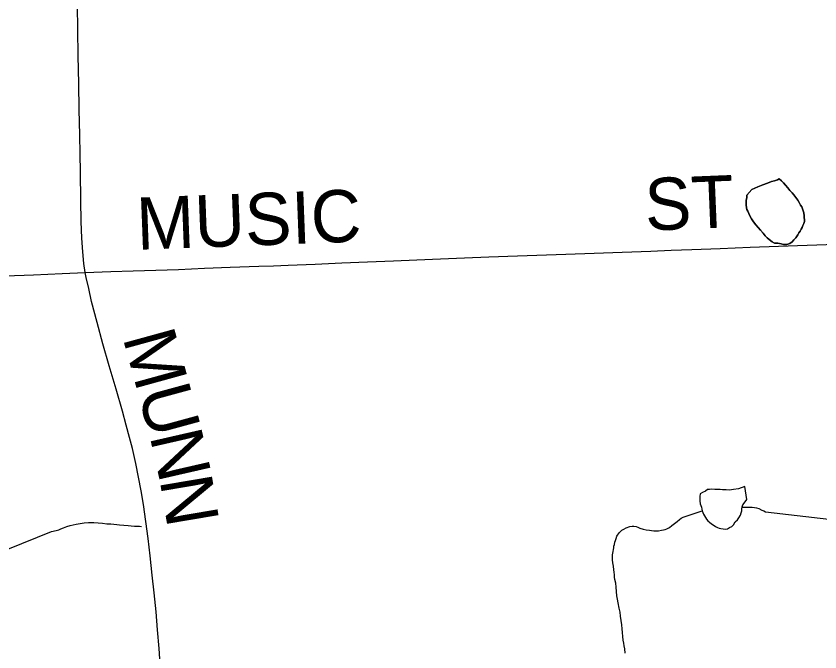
# Model space of a CAD drawing. Extents: x 103424 to 290657, y 38711 to 110967.
# Drawn here: x 126106 to 130753, y 49490 to 53166 of the extents above; entities that cross this region are included whole.
import ezdxf

# ---------------------------------------------------------------- set-up
doc = ezdxf.new("R2010")
doc.units = 0
for name, color, linetype in [('GM_X_Minor_Lake', 7, 'Continuous'), ('GM_X_Minor_River', 7, 'Continuous'), ('GM_X_Township_Road', 7, 'Continuous'), ('GM_X_Township_Road_Text', 7, 'Continuous')]:
    doc.layers.add(name, color=color, linetype=linetype)

msp = doc.modelspace()

# ---------------------------------------------------------------- linework, layer by layer
at = {"layer": 'GM_X_Minor_Lake'}
for points in [[(130359.8, 52163), (130393.8, 52179.7), (130423.9, 52190.3), (130450, 52200.8), (130474.1, 52209.3), (130490.1, 52213.6), (130508.2, 52219.9), (130518.2, 52224.2), (130530.5, 52214.2), (130542.8, 52202.3), (130555.1, 52188.4), (130567.5, 52172.4), (130579.9, 52158.5), (130592.2, 52144.6), (130602.5, 52132.6), (130614.9, 52116.6), (130625.2, 52102.7), (130633.5, 52088.7), (130641.8, 52072.6), (130648.1, 52062.6), (130652.3, 52052.6), (130660.7, 52028.5), (130663.1, 52010.4), (130663.2, 52000.3), (130663.4, 51990.2), (130663.6, 51978.1), (130659.8, 51965.9), (130653.9, 51955.7), (130650.1, 51943.5), (130644.2, 51933.3), (130638.3, 51923.1), (130632.4, 51912.9), (130626.6, 51900.7), (130614.7, 51884.3), (130602.8, 51872), (130592.9, 51861.8), (130579, 51851.4), (130562.9, 51845.1), (130542.8, 51844.8), (130528.6, 51848.6), (130510.3, 51852.3), (130490.1, 51854), (130477.9, 51859.9), (130459.5, 51873.7), (130449.3, 51883.6), (130437, 51895.6), (130424.6, 51911.5), (130410.2, 51927.4), (130395.8, 51943.4), (130383.4, 51959.3), (130369, 51977.3), (130358.6, 51993.3), (130348.2, 52011.3), (130342, 52025.3), (130335.7, 52037.3), (130331.5, 52047.4), (130329.3, 52057.4), (130327, 52075.6), (130326.5, 52101.8), (130330.3, 52116), (130330.1, 52130.2), (130359.8, 52163)], [(130638.3, 51923.1), (130644.2, 51933.3), (130650.1, 51943.5), (130653.9, 51955.7), (130659.8, 51965.9), (130663.6, 51978.1), (130663.4, 51990.2), (130663.2, 52000.3), (130663.1, 52010.4), (130660.7, 52028.5), (130652.3, 52052.6), (130648.1, 52062.6), (130641.8, 52072.6), (130633.5, 52088.7), (130625.2, 52102.7), (130614.9, 52116.6), (130602.5, 52132.6), (130592.2, 52144.6), (130579.9, 52158.5), (130567.5, 52172.4), (130555.1, 52188.4), (130542.8, 52202.3), (130530.5, 52214.2), (130518.2, 52224.2), (130508.2, 52219.9), (130490.1, 52213.6), (130474.1, 52209.3), (130450, 52200.8), (130423.9, 52190.3), (130393.8, 52179.7), (130359.8, 52163)], [(130359.8, 52163), (130330.1, 52130.2), (130330.3, 52116), (130326.5, 52101.8), (130327, 52075.6), (130329.3, 52057.4), (130331.5, 52047.4), (130335.7, 52037.3), (130342, 52025.3), (130348.2, 52011.3), (130358.6, 51993.3), (130369, 51977.3), (130383.4, 51959.3), (130395.8, 51943.4), (130410.2, 51927.4), (130424.6, 51911.5), (130437, 51895.6), (130449.3, 51883.6), (130459.5, 51873.7), (130477.9, 51859.9), (130490.1, 51854), (130510.3, 51852.3), (130528.6, 51848.6), (130542.8, 51844.8), (130562.9, 51845.1), (130579, 51851.4), (130592.9, 51861.8), (130602.8, 51872), (130614.7, 51884.3), (130626.6, 51900.7), (130632.4, 51912.9), (130638.3, 51923.1)], [(130320.1, 50445.3), (130282, 50432.5), (130253.8, 50428), (130229.7, 50425.6), (130211.5, 50427.3), (130189.3, 50427), (130177.1, 50428.8), (130163, 50428.6), (130144.9, 50428.3), (130126.7, 50430), (130114.6, 50429.8), (130102.5, 50429.6), (130092.5, 50419.3), (130074.5, 50411), (130060.5, 50404.7), (130058.8, 50388.5), (130059.2, 50364.2), (130061.5, 50346.1), (130065.7, 50336.1), (130067.9, 50326), (130070.1, 50315.9), (130072.3, 50305.9), (130076.5, 50295.8), (130080.7, 50285.8), (130086.9, 50275.8), (130097.3, 50257.8)], [(130320.1, 50445.3), (130282, 50432.5), (130253.8, 50428), (130229.7, 50425.6), (130211.5, 50427.3), (130189.3, 50427), (130177.1, 50428.8), (130163, 50428.6), (130144.9, 50428.3), (130126.7, 50430), (130114.6, 50429.8), (130102.5, 50429.6), (130092.5, 50419.3), (130074.5, 50411), (130060.5, 50404.7), (130058.8, 50388.5), (130059.2, 50364.2), (130061.5, 50346.1), (130065.7, 50336.1), (130067.9, 50326), (130070.1, 50315.9), (130072.3, 50305.9), (130076.5, 50295.8), (130080.7, 50285.8), (130086.9, 50275.8), (130097.3, 50257.8), (130105.5, 50247.8), (130115.8, 50239.9), (130126, 50230), (130136.2, 50224.1), (130150.5, 50214.2), (130160.7, 50208.3), (130170.8, 50204.5), (130180.9, 50202.6), (130193.1, 50200.8), (130209.3, 50199), (130219.3, 50201.2), (130231.3, 50209.5), (130243.3, 50215.8), (130253.2, 50224), (130263, 50242.3), (130277, 50252.7), (130284.8, 50264.9), (130294.6, 50281.2), (130298.5, 50293.4), (130302.3, 50305.6), (130302.1, 50317.7), (130304, 50327.8), (130307.8, 50340), (130321.6, 50358.4), (130331.5, 50370.7), (130320.1, 50445.3)], [(130097.3, 50257.8), (130105.5, 50247.8), (130115.8, 50239.9), (130126, 50230), (130136.2, 50224.1), (130150.5, 50214.2), (130160.7, 50208.3), (130170.8, 50204.5), (130180.9, 50202.6), (130193.1, 50200.8), (130209.3, 50199), (130219.3, 50201.2), (130231.3, 50209.5), (130243.3, 50215.8), (130253.2, 50224), (130263, 50242.3), (130277, 50252.7), (130284.8, 50264.9), (130294.6, 50281.2), (130298.5, 50293.4), (130302.3, 50305.6), (130302.1, 50317.7), (130304, 50327.8), (130307.8, 50340), (130321.6, 50358.4), (130331.5, 50370.7), (130320.1, 50445.3)]]:
    msp.add_lwpolyline(points, dxfattribs=at)
at = {"layer": 'GM_X_Minor_River'}
for points in [[(129628.1, 49482.5), (129625.6, 49506.7), (129621.3, 49524.8), (129619, 49540.9), (129616.7, 49557.1), (129614.3, 49579.3), (129611.9, 49601.4), (129609.5, 49623.6), (129607.2, 49645.8), (129604.7, 49672), (129600.3, 49696.2), (129597.8, 49720.4), (129593.4, 49742.5), (129586.9, 49772.7), (129582.4, 49794.9), (129580.1, 49815), (129577.7, 49839.2), (129575.2, 49863.4), (129572.8, 49887.6), (129568.4, 49907.8), (129566.2, 49921.9), (129565.9, 49936), (129563.7, 49950.1), (129561.4, 49964.2), (129559, 49986.4), (129556.7, 50004.5), (129554.4, 50022.7), (129554.1, 50038.8), (129553.9, 50050.9), (129555.8, 50061.1), (129557.6, 50071.2), (129559.4, 50081.3), (129561.3, 50091.5), (129561.1, 50101.6), (129565, 50111.7), (129566.8, 50123.9), (129570.7, 50134), (129574.5, 50146.2), (129578.3, 50158.4), (129592.1, 50178.8), (129608, 50193.2), (129620, 50199.5), (129634, 50207.8), (129654.1, 50214.2), (129668.2, 50216.4), (129678.3, 50216.6), (129690.4, 50214.8), (129700.5, 50210.9), (129712.7, 50205), (129731, 50199.3), (129749.2, 50195.5), (129767.4, 50193.8), (129779.6, 50192), (129793.7, 50190.2), (129819.9, 50190.6), (129838.1, 50193), (129848.1, 50195.1), (129858.2, 50197.3), (129868.2, 50201.5), (129884.2, 50209.9), (129898.1, 50220.2), (129912.1, 50232.5), (129928, 50242.9), (129941.9, 50255.3), (129951.9, 50263.5), (129961.9, 50269.7), (130072.3, 50305.9)], [(130303.9, 50327.5), (130348.4, 50326.6), (130362.5, 50326.8), (130374.6, 50325), (130386.8, 50323.1), (130401, 50319.3), (130417.3, 50309.5), (130429.4, 50305.7), (130439.6, 50299.8)], [(130439.6, 50299.8), (130805.6, 50257.3)], [(126058.3, 50084.6), (126310.8, 50185.6), (126336.9, 50192.1), (126353, 50196.4), (126365, 50200.7), (126379.1, 50207), (126399.1, 50215.4), (126419.2, 50219.8), (126435.3, 50224.1), (126453.4, 50228.4), (126475.5, 50232.8), (126499.7, 50235.2), (126523.8, 50237.6), (126556.1, 50238.1), (126580.4, 50236.5), (126604.6, 50234.9), (126630.9, 50231.3), (126653.1, 50229.6), (126671.3, 50227.9), (126687.5, 50226.2), (126703.7, 50224.4), (126754.2, 50221.2), (126770.3, 50219.4), (126790.5, 50217.8), (126806.7, 50216), (126818.8, 50216.2), (126831, 50214.4)]]:
    msp.add_lwpolyline(points, dxfattribs=at)
at = {"layer": 'GM_X_Township_Road'}
for points in [[(126940.8, 49388.5), (126932.5, 49508.7), (126923.7, 49618.1), (126914.9, 49722.3), (126904, 49831.7), (126892.6, 49934.3), (126880.7, 50045.2), (126869.3, 50146.3), (126856.8, 50244.8), (126842.8, 50341.2), (126828.8, 50421), (126814.4, 50499.3), (126798.3, 50579.6), (126778.6, 50666.7), (126762, 50729.9), (126742.8, 50800.9), (126721.1, 50880.9), (126685.1, 51009.4), (126643.8, 51144), (126607, 51271), (126574.9, 51394.9), (126542.7, 51516.7), (126526.2, 51590.3), (126510.6, 51654.6), (126504.9, 51683.6), (126497.1, 51736.5), (126491.9, 51803.3), (126486.2, 51882.1), (126482.4, 51979.1), (126480.4, 52099.4), (126477.6, 52263.2), (126475.8, 52370.6), (126474.1, 52478.1), (126471.3, 52626), (126468.6, 52773.9), (126465.5, 52939), (126462.8, 53085), (126460.1, 53231.1)], [(126504.9, 51683.6), (126654.2, 51688.8), (126783.3, 51693.5), (126914.3, 51697.6), (127045.3, 51701.8), (127194.6, 51707.8), (127343.8, 51713.7), (127508.8, 51719.6), (127594, 51722.7), (127679.1, 51725.7), (127834.4, 51732.2), (127989.6, 51738.6), (128138.4, 51745), (128287.2, 51751.5), (128423, 51757), (128558.9, 51762.4), (128699.4, 51768), (128839.9, 51773.7), (129004.8, 51779.9), (129116.7, 51784.1), (129228.7, 51788.3), (129393.6, 51793.9), (129502.3, 51797.6), (129611, 51801.3), (129775.9, 51807.7), (129894.3, 51812.3), (130012.6, 51816.9), (130177.6, 51823.1), (130263.7, 51826.3), (130349.8, 51829.6), (130514.7, 51835.8), (130679.7, 51842), (130844.6, 51847.5)], [(126042.1, 51664), (126206.9, 51670.4), (126371.7, 51676.9), (126504.9, 51683.6)]]:
    msp.add_lwpolyline(points, dxfattribs=at)

# ---------------------------------------------------------------- texts
at = {"layer": 'GM_X_Township_Road_Text'}
for s, height, rotation, p in [('ST', 301.87, 2.335, (129746.2, 51925.1)), ('MUSIC', 301.87, 2.1612, (126806.5, 51814.4)), ('M', 301.9, 285.3953, (126721, 51308.6)), ('U', 301.9, 285.2459, (126807.9, 50993)), ('N', 301.9, 282.8761, (126877, 50739.9)), ('N', 301.9, 279.5887, (126935.3, 50485.4))]:
    msp.add_text(s, height=height, rotation=rotation, dxfattribs=at).set_placement(p)

doc.saveas('drawing.dxf')
